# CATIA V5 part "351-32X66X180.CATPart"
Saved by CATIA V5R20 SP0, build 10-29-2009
Part number: 351-32X66X180
Definition: NONE
Nomenclature: 351-32X66X180
Source: Unknown
Description: 351-32X66X180
Bounding box of the stored display mesh (mm): x -7 to 173, y -22.5 to 22.5, z -22.5 to 22.5
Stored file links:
  C:\Users\Utente\Desktop\IO LAVORO\3D X SITO CF\X SITO\PLASTICA\351\351-32X66X180.CATPart
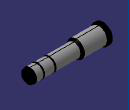
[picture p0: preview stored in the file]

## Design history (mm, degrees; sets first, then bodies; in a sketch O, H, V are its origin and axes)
Body1 "351-32X66X180" (main body)
  Solid1: solid without history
